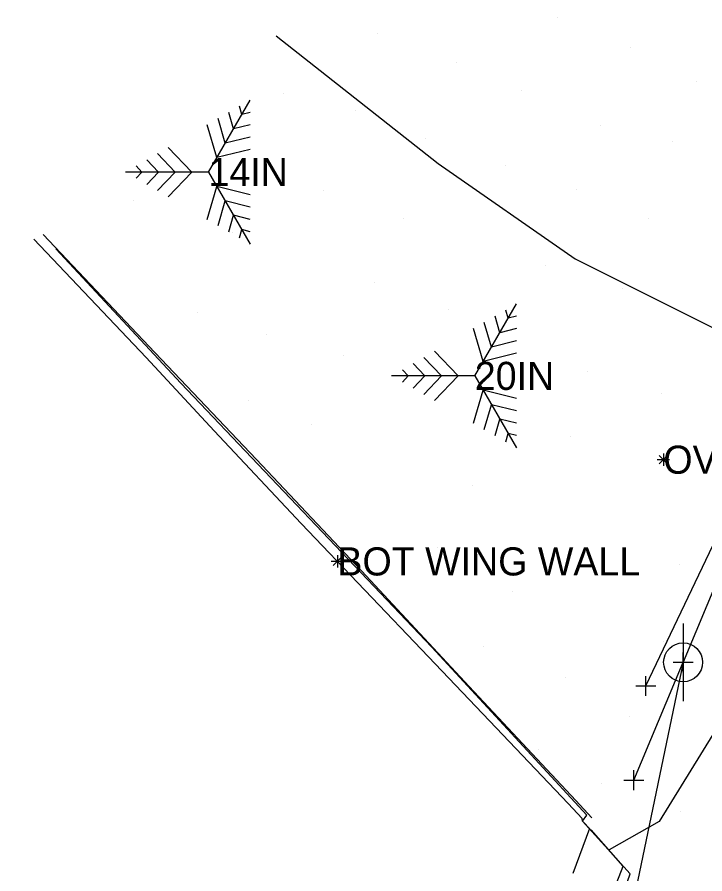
# Model space of a CAD drawing. Extents: x 1729983 to 1730242, y 468641 to 469019.
# Drawn here: x 1730042.9 to 1730086.9, y 468913 to 468967.9 of the extents above; entities that cross this region are included whole.
import ezdxf

# ---------------------------------------------------------------- set-up
doc = ezdxf.new("R2010")
doc.units = 0
for name, color, linetype in [('Default', 7, 'Continuous'), ('S_Bridge_Abutment_Bottom', 7, 'Continuous'), ('S_Bridge_Wingwall', 7, 'Continuous'), ('S_Ground_LevelString', 7, 'Continuous'), ('S_Ground_SpotElevation', 7, 'Continuous'), ('S_Misc_MiscFeature', 7, 'Continuous'), ('S_Misc_MiscItems', 7, 'Continuous'), ('S_Survey_Shot', 7, 'Continuous'), ('S_Text', 7, 'Continuous'), ('S_Trees_Bush_Line', 7, 'Continuous'), ('S_Trees_Conifer_Pay', 7, 'Continuous'), ('S_Utilities_AG_Communications', 7, 'Continuous'), ('S_Utilities_GuyWire3', 7, 'Continuous'), ('S_Utilities_Pole_Power', 7, 'Continuous')]:
    doc.layers.add(name, color=color, linetype=linetype)

# ---------------------------------------------------------------- blocks, each defined once
blk = doc.blocks.new('POINT_DISPLAY')
at = {"layer": 'Default'}
blk.add_line((0, 0), (0, 0), dxfattribs=at)

msp = doc.modelspace()

# ---------------------------------------------------------------- linework, layer by layer
at = {"layer": 'S_Bridge_Abutment_Bottom'}
msp.add_lwpolyline([(1730028.397, 468777.334), (1730030.386, 468778.233), (1730033.055, 468779.454), (1730033.218, 468779.896), (1730038.37, 468793.886), (1730045.609, 468813.805), (1730053.552, 468835.326), (1730061.264, 468856.585), (1730068.104, 468874.933), (1730077.288, 468899.639), (1730081.24, 468910.357), (1730081.674, 468911.604), (1730082.174, 468913.008), (1730079.112, 468916.385)], dxfattribs=at)
at = {"layer": 'S_Bridge_Wingwall'}
msp.add_lwpolyline([(1730079.111, 468916.384), (1730079.383, 468916.768), (1730069.47, 468927.525), (1730053.394, 468944.426), (1730045.376, 468953.015)], dxfattribs=at)
at = {"layer": 'S_Ground_LevelString'}
msp.add_lwpolyline([(1730044.577, 468953.94), (1730051.732, 468946.379), (1730058.225, 468939.521), (1730064.949, 468932.412), (1730071.861, 468925.004), (1730078.683, 468917.692), (1730079.71, 468916.591)], dxfattribs=at)
at = {"layer": 'S_Misc_MiscFeature'}
for points in [[(1730079.112, 468916.385), (1730079.088, 468916.552), (1730078.184, 468917.506), (1730073.577, 468922.347), (1730069.239, 468926.893), (1730061.1, 468935.438), (1730055.514, 468941.366), (1730051.166, 468946.064), (1730043.973, 468953.64)], [(1730079.111, 468916.384), (1730079.184, 468916.31), (1730079.561, 468915.895), (1730078.502, 468913.017)], [(1730028.819, 468777.529), (1730031.975, 468779.199), (1730034.887, 468787.021), (1730045.144, 468814.963), (1730055.236, 468842.487), (1730058.712, 468851.879), (1730068.635, 468878.922), (1730072.147, 468888.181), (1730075.727, 468897.903), (1730078.619, 468905.503), (1730081.717, 468913.484), (1730079.668, 468915.827)]]:
    msp.add_lwpolyline(points, dxfattribs=at)
at = {"layer": 'S_Misc_MiscItems'}
for p, q in [((1730084.552, 468939.258), (1730084.028, 468939.782)), ((1730084.552, 468939.782), (1730084.028, 468939.258)), ((1730084.29, 468939.913), (1730084.29, 468939.127)), ((1730084.683, 468939.52), (1730083.897, 468939.52)), ((1730063.678, 468932.744), (1730063.154, 468933.268)), ((1730063.678, 468933.268), (1730063.154, 468932.744)), ((1730063.416, 468933.399), (1730063.416, 468932.613)), ((1730063.809, 468933.006), (1730063.023, 468933.006))]:
    msp.add_line(p, q, dxfattribs=at)
at = {"layer": 'S_Survey_Shot'}
for p, q in [((1730085.557, 468925.91), (1730085.555, 468927.182)), ((1730084.92, 468926.545), (1730086.192, 468926.547)), ((1730085.556, 468926.546), (1730085.556, 468926.546)), ((1730083.168, 468924.395), (1730083.166, 468925.667)), ((1730082.531, 468925.03), (1730083.803, 468925.032)), ((1730083.167, 468925.031), (1730083.167, 468925.031)), ((1730082.4, 468918.367), (1730082.398, 468919.639)), ((1730081.763, 468919.002), (1730083.035, 468919.004)), ((1730082.399, 468919.003), (1730082.399, 468919.003))]:
    msp.add_line(p, q, dxfattribs=at)
at = {"layer": 'S_Trees_Bush_Line'}
msp.add_lwpolyline([(1730059.491, 468966.653), (1730069.864, 468958.481), (1730078.631, 468952.373), (1730087.606, 468947.904), (1730094.366, 468942.3), (1730094.314, 468936.887), (1730092.999, 468931.526), (1730087.455, 468921.933), (1730084.021, 468916.346), (1730080.816, 468914.539)], dxfattribs=at)
at = {"layer": 'S_Trees_Conifer_Pay'}
for p, q in [((1730055.16, 468957.936), (1730057.823, 468962.547)), ((1730057.289, 468961.624), (1730057.139, 468962.153)), ((1730056.755, 468960.7), (1730056.454, 468961.756)), ((1730057.823, 468961.756), (1730057.289, 468961.624)), ((1730056.226, 468959.78), (1730055.769, 468961.359)), ((1730055.692, 468958.859), (1730055.085, 468960.965)), ((1730057.823, 468960.965), (1730056.755, 468960.7)), ((1730057.823, 468960.177), (1730056.226, 468959.78)), ((1730054.094, 468957.936), (1730052.574, 468959.518)), ((1730057.823, 468959.383), (1730055.692, 468958.859)), ((1730053.031, 468957.936), (1730051.89, 468959.121)), ((1730050.899, 468957.936), (1730050.521, 468958.33)), ((1730051.965, 468957.936), (1730051.205, 468958.724)), ((1730055.16, 468957.936), (1730049.836, 468957.936)), ((1730050.521, 468957.542), (1730050.899, 468957.936)), ((1730051.205, 468957.145), (1730051.965, 468957.936)), ((1730051.89, 468956.748), (1730053.031, 468957.936)), ((1730052.574, 468956.354), (1730054.094, 468957.936)), ((1730055.16, 468957.936), (1730057.823, 468953.325)), ((1730055.085, 468954.907), (1730055.692, 468957.013)), ((1730057.823, 468956.486), (1730055.692, 468957.013)), ((1730055.769, 468954.51), (1730056.226, 468956.09)), ((1730057.823, 468955.695), (1730056.226, 468956.09)), ((1730056.454, 468954.113), (1730056.755, 468955.169)), ((1730057.823, 468954.907), (1730056.755, 468955.169)), ((1730057.139, 468953.719), (1730057.289, 468954.248)), ((1730057.823, 468954.113), (1730057.289, 468954.248)), ((1730072.214, 468944.884), (1730074.877, 468949.495)), ((1730074.343, 468948.572), (1730074.193, 468949.101)), ((1730073.809, 468947.648), (1730073.508, 468948.704)), ((1730074.877, 468948.704), (1730074.343, 468948.572)), ((1730072.746, 468945.807), (1730072.139, 468947.913)), ((1730073.28, 468946.728), (1730072.823, 468948.307)), ((1730074.877, 468947.913), (1730073.809, 468947.648)), ((1730074.877, 468947.125), (1730073.28, 468946.728)), ((1730071.148, 468944.884), (1730069.628, 468946.466)), ((1730074.877, 468946.331), (1730072.746, 468945.807)), ((1730069.019, 468944.884), (1730068.259, 468945.672)), ((1730070.085, 468944.884), (1730068.944, 468946.069)), ((1730067.953, 468944.884), (1730067.575, 468945.278)), ((1730072.214, 468944.884), (1730066.89, 468944.884)), ((1730067.575, 468944.49), (1730067.953, 468944.884)), ((1730068.259, 468944.093), (1730069.019, 468944.884)), ((1730068.944, 468943.696), (1730070.085, 468944.884)), ((1730069.628, 468943.302), (1730071.148, 468944.884)), ((1730072.214, 468944.884), (1730074.877, 468940.273)), ((1730072.139, 468941.855), (1730072.746, 468943.961)), ((1730074.877, 468943.434), (1730072.746, 468943.961)), ((1730072.823, 468941.458), (1730073.28, 468943.038)), ((1730074.877, 468942.643), (1730073.28, 468943.038)), ((1730073.508, 468941.061), (1730073.809, 468942.117)), ((1730074.877, 468941.855), (1730073.809, 468942.117)), ((1730074.193, 468940.667), (1730074.343, 468941.196)), ((1730074.877, 468941.061), (1730074.343, 468941.196))]:
    msp.add_line(p, q, dxfattribs=at)
at = {"layer": 'S_Utilities_AG_Communications'}
msp.add_lwpolyline([(1730120.945, 469004.632), (1730097.184, 468954.408), (1730085.556, 468926.546), (1730082.304, 468910.964), (1730034.658, 468781.323), (1729998.254, 468703.261)], dxfattribs=at)
at = {"layer": 'S_Utilities_GuyWire3'}
for points in [[(1730083.167, 468925.031), (1730097.184, 468954.408)], [(1730082.399, 468919.003), (1730085.556, 468926.546)]]:
    msp.add_lwpolyline(points, dxfattribs=at)
at = {"layer": 'S_Utilities_Pole_Power'}
msp.add_line((1730085.556, 468929.041), (1730085.556, 468924.051), dxfattribs=at)
msp.add_circle((1730085.556, 468926.546), 1.248, dxfattribs=at)

# ---------------------------------------------------------------- block references
at = {"layer": 'S_Ground_SpotElevation'}
for p in [(1730077.491, 468967.847), (1730066.012, 468966.778), (1730082.184, 468965.895), (1730071.014, 468964.962), (1730086.442, 468963.713), (1730059.953, 468962.959), (1730075.23, 468963.134), (1730064.555, 468961.851), (1730080.278, 468960.927), (1730069.029, 468960.063), (1730084.885, 468959.922), (1730058.232, 468958.472), (1730074.185, 468958.356), (1730062.545, 468956.737), (1730078.706, 468956.817), (1730050.384, 468956.144), (1730067.679, 468954.94), (1730083.324, 468954.938), (1730056.693, 468954.068), (1730076.763, 468951.951), (1730065.796, 468950.873), (1730081.694, 468950.477), (1730054.476, 468948.941), (1730070.542, 468949.154), (1730086.336, 468948.503), (1730058.903, 468947.507), (1730063.782, 468946.206), (1730079.41, 468945.174), (1730084.177, 468943.766), (1730057.702, 468943.332), (1730073.496, 468942.663), (1730061.744, 468941.747), (1730078.335, 468940.973), (1730072.037, 468937.836), (1730060.902, 468936.59), (1730069.853, 468933.92), (1730085.325, 468932.791), (1730074.648, 468931.061), (1730068.281, 468928.791), (1730072.758, 468927.574), (1730084.322, 468927.908), (1730078.037, 468925.556), (1730082.1, 468923.046), (1730076.268, 468920.95), (1730080.352, 468918.764), (1730085.403, 468917.005)]:
    msp.add_blockref('POINT_DISPLAY', p, dxfattribs=at)

# ---------------------------------------------------------------- texts
at = {"layer": 'S_Text'}
for s, p in [('14IN', (1730055.16, 468957.036)), ('20IN', (1730072.214, 468943.984)), ('OVERGROWTH', (1730084.29, 468938.62)), ('BOT WING WALL', (1730063.416, 468932.106))]:
    msp.add_text(s, height=1.8, dxfattribs=at).set_placement(p)

doc.saveas('drawing.dxf')
